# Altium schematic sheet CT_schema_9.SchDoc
size 391 x 238 mm
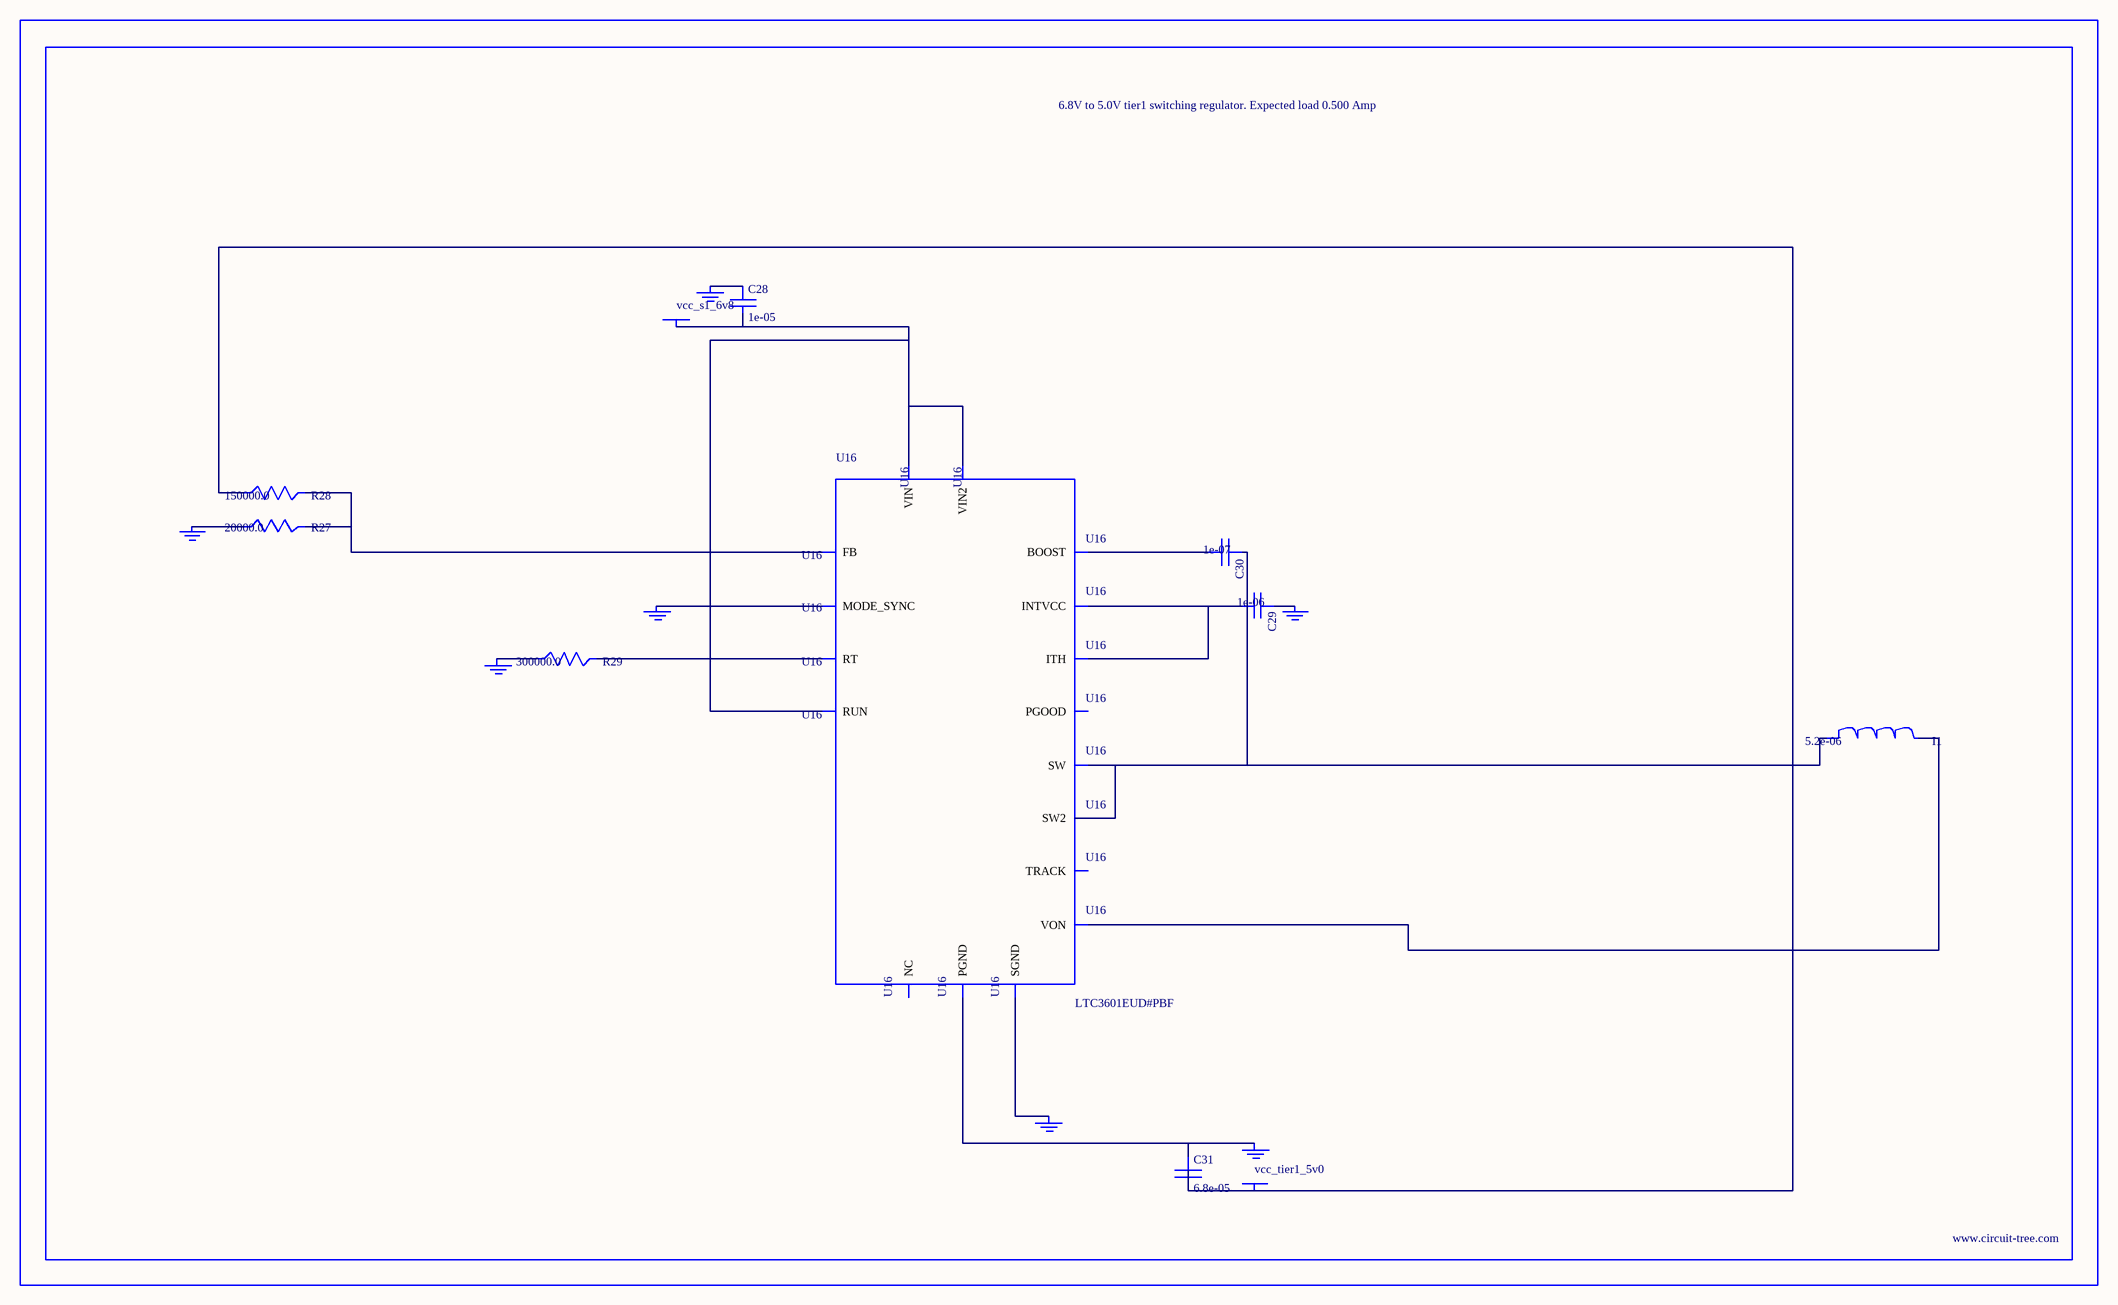
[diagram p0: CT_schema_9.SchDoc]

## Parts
BORDER8  (no value)
C28  1e-05  [C0805]
C29  1e-06  [C0603]
C30  1e-07  [C0402]
C31  6.8e-05  [2220]
GND_INSTANCE_8_0  (no value)
GND_INSTANCE_8_1  (no value)
GND_INSTANCE_8_2  (no value)
GND_INSTANCE_8_3  (no value)
GND_INSTANCE_8_4  (no value)
GND_INSTANCE_8_5  (no value)
GND_INSTANCE_8_6  (no value)
I1  5.2e-06  [DR1040]
POWER_INSTANCE_8_0  vcc_s1_6v8
POWER_INSTANCE_8_1  vcc_tier1_5v0
R27  20000.0  [R0603]
R28  150000.0  [R0603]
R29  300000.0  [R0603]
U16  LTC3601EUD#PBF  [QFN-16_EP]

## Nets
NetC28_1: C28.1 GND_INSTANCE_8_5.0(GND)
NetC28_2: C28.2 POWER_INSTANCE_8_0.0(PWR) U16.14(RUN) U16.15(VIN) U16.16(VIN2)
NetC29_1: C29.1 GND_INSTANCE_8_1.0(GND)
NetC29_2: C29.2 U16.7(INTVCC) U16.12(ITH)
NetC30_1: C30.1 I1.1 U16.3(SW) U16.4(SW2)
NetC30_2: C30.2 U16.6(BOOST)
NetC31_1: C31.1 GND_INSTANCE_8_6.0(GND) U16.17(PGND)
NetC31_2: C31.2 I1.2 POWER_INSTANCE_8_1.0(PWR) R28.1 U16.8(VON)
NetGND_INSTANCE_8_0_0: GND_INSTANCE_8_0.0(GND) U16.1(MODE_SYNC)
NetGND_INSTANCE_8_2_0: GND_INSTANCE_8_2.0(GND) U16.9(SGND)
NetGND_INSTANCE_8_3_0: GND_INSTANCE_8_3.0(GND) R29.1
NetGND_INSTANCE_8_4_0: GND_INSTANCE_8_4.0(GND) R27.1
NetR27_2: R27.2 R28.2 U16.11(FB)
NetR29_2: R29.2 U16.10(RT)

Not connected (* = marked no-connect by the designer): U16 2(PGOOD) 5(NC) 13(TRACK)

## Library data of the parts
BORDER8 = BORDER_PAGE8
C28 = C0805C106K8RACTU
C29 = C0603C105K3RACTU
C30 = C0402C104K3RACTU
C31 = C5750X5R1A686M
GND_INSTANCE_8_0-GND_INSTANCE_8_6 = GND
I1 = DR1040-5R2-R
POWER_INSTANCE_8_0 POWER_INSTANCE_8_1 = PWR
R27 = RC0603JR-0720KL
R28 = RC0603JR-07150KL
R29 = RC0603JR-07300KL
